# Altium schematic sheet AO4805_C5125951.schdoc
size 127 x 101 mm
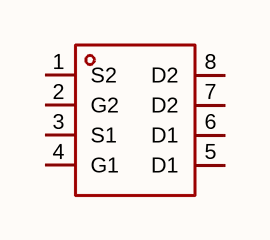
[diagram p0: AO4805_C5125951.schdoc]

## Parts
Q?  ao4805_c5125951  [SOP-8_L4.9-W3.9-P1.27-LS6.0-BL]  (value not drawn)

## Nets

Not connected (* = marked no-connect by the designer): Q? 1(S2) 2(G2) 3(S1) 4(G1) 5(D1) 6(D1) 7(D2) 8(D2)

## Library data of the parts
Q? = ao4805_c5125951: 数量:2个P沟道;漏源电压(Vdss):30V;连续漏极电流(Id):8A;导通电阻(RDS(on)):12mΩ@10V；16mΩ@4.5V;耗散功率(Pd):1.44W;阈值电压(Vgs(th)):1.5V@250uA;; Manufacturer: UMW(友台半导体); ManufacturerPart: AO4805; AddInBom: yes; ModelId: 75c24a7891ee4dd6bdac16a7163ff87e; ModelName: SOP-8_L4.9-W3.9-P1.27-LS6.0-BL-1; ModelTransform: 192.913,236.22,0,0,0,0,-0.393,2.749,0; Number: 2个P沟道; Drain to Source Voltage: 30V; Current - Continuous Drain(Id): 8A; Pd - Power Dissipation: 1.44W; Gate Charge(Qg): 39nC@10V; Input Capacitance(Ciss): 2.076nF; Reverse Transfer Capacitance (Crss@Vds): 302pF; Output Capacitance(Coss): 503pF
